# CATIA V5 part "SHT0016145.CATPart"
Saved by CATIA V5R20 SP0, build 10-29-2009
Part number: SHT0016145
Bounding box of the stored display mesh (mm): x -544.085 to -428.061, y -861 to -597, z 2.9 to 106.4
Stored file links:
  C:\Users\hp\Desktop\SHT0016145-宽车主驾驶前侧钣金\SHT0016145.CATPart
  C:\Users\hp\Desktop\SHT0016014-宽车主驾驶底部支架焊接总成\SHT0016014.CATPart
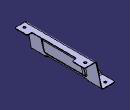
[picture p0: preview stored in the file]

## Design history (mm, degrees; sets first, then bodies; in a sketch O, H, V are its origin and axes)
Body1 (main body)
Body2 "SHT0016145-宽车主驾驶前侧钣金"
  Solid1: solid without history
